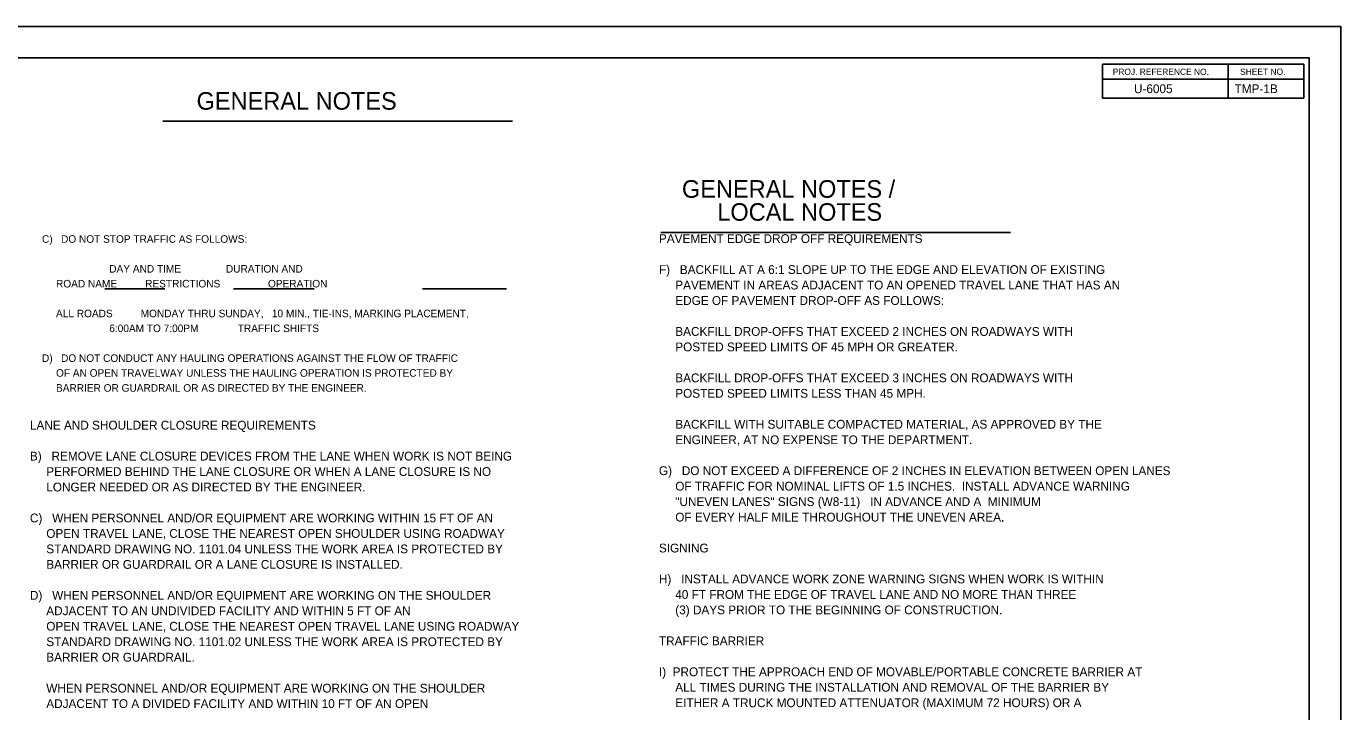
# Model space of a CAD drawing. Extents: x 762655 to 770567, y 650864 to 655190.
# Drawn here: x 769522 to 770567, y 654645 to 655190 of the extents above; entities that cross this region are included whole.
import ezdxf

# ---------------------------------------------------------------- set-up
doc = ezdxf.new("R2010")
doc.units = 0
for name, color, linetype in [('Default', 7, 'Continuous'), ('DEV BORDER CELL', 7, 'Continuous'), ('DEV TRANSPORTATION OPERATIONS PLAN SHEET', 7, 'Continuous'), ('Text', 7, 'Continuous')]:
    doc.layers.add(name, color=color, linetype=linetype)

msp = doc.modelspace()

# ---------------------------------------------------------------- linework, layer by layer
at = {"layer": 'Default'}
for p, q in [((769584.4, 654981.1), (769632.1, 654981.1)), ((769836.8, 654981.1), (769903.6, 654981.1))]:
    msp.add_line(p, q, dxfattribs=at)
at = {"layer": 'DEV BORDER CELL'}
for p, q in [((769630.5, 655114.3), (769908.5, 655114.3)), ((770026.5, 655026), (770304.4, 655026))]:
    msp.add_line(p, q, dxfattribs=at)
at = {"layer": 'DEV TRANSPORTATION OPERATIONS PLAN SHEET'}
msp.add_line((770477.6, 655147.7), (770537.6, 655147.7), dxfattribs=at)
for points in [[(770542, 655164.8), (769042, 655164.8), (769042, 654114.8), (770542, 654114.8)], [(770377.6, 655159.7), (770477.6, 655159.7), (770477.6, 655147.7), (770377.6, 655147.7)], [(770477.6, 655147.7), (770537.6, 655147.7), (770537.6, 655159.7), (770477.6, 655159.7)], [(770477.6, 655147.7), (770377.6, 655147.7), (770377.6, 655132.7), (770477.6, 655132.7)], [(770477.6, 655147.7), (770537.6, 655147.7), (770537.6, 655132.7), (770477.6, 655132.7)]]:
    msp.add_lwpolyline(points, close=True, dxfattribs=at)
at = {"layer": 'Text'}
msp.add_line((769686.7, 654981.1), (769750.9, 654981.1), dxfattribs=at)
msp.add_lwpolyline([(768879, 654089.8), (770567, 654089.8), (770567, 655189.8), (768879, 655189.8)], close=True, dxfattribs=at)

# ---------------------------------------------------------------- texts
at = {"layer": 'DEV TRANSPORTATION OPERATIONS PLAN SHEET'}
for s, height, p in [('PROJ. REFERENCE NO.', 4.999, (770385.7, 655151.2)), ('SHEET NO.', 5, (770487, 655151.2))]:
    msp.add_text(s, height=height, rotation=0.0006, dxfattribs=at).set_placement(p)
for s, height, p in [('U-6005', 7, (770402.6, 655136.7)), ('TMP-1B  ', 7, (770482.6, 655136.7)), ('GENERAL NOTES', 14, (769657.3, 655123.5)), ('GENERAL NOTES / ', 14, (770043.2, 655053.5)), ('LOCAL NOTES', 14, (770071.3, 655035.2))]:
    msp.add_text(s, height=height, dxfattribs=at).set_placement(p)
at = {"layer": 'Text'}
for s, height, p in [('       C)   DO NOT STOP TRAFFIC AS FOLLOWS:  ', 6, (769518.8, 655017.7)), ('       PAVEMENT EDGE DROP OFF REQUIREMENTS', 7, (770006.7, 655017.5)), ('                               DAY AND TIME                DURATION AND', 6, (769518.8, 654994)), ('       F)   BACKFILL AT A 6:1 SLOPE UP TO THE EDGE AND ELEVATION OF EXISTING', 7, (770006.7, 654992.9)), ('            ROAD NAME          RESTRICTIONS                 OPERATION', 6, (769518.8, 654982.2)), ('            PAVEMENT IN AREAS ADJACENT TO AN OPENED TRAVEL LANE THAT HAS AN ', 7, (770006.7, 654980.6)), ('            EDGE OF PAVEMENT DROP-OFF AS FOLLOWS:', 7, (770006.7, 654968.3)), ('            ALL ROADS          MONDAY THRU SUNDAY,   10 MIN., TIE-INS, MARKING PLACEMENT,', 6, (769518.8, 654958.5)), ('                               6:00AM TO 7:00PM              TRAFFIC SHIFTS', 6, (769518.8, 654946.7)), ('            BACKFILL DROP-OFFS THAT EXCEED 2 INCHES ON ROADWAYS WITH', 7, (770006.7, 654943.7)), ('       D)   DO NOT CONDUCT ANY HAULING OPERATIONS AGAINST THE FLOW OF TRAFFIC', 6, (769518.8, 654923)), ('            POSTED SPEED LIMITS OF 45 MPH OR GREATER.', 7, (770006.7, 654931.4)), ('            OF AN OPEN TRAVELWAY UNLESS THE HAULING OPERATION IS PROTECTED BY', 6, (769518.8, 654911.2)), ('            BACKFILL DROP-OFFS THAT EXCEED 3 INCHES ON ROADWAYS WITH', 7, (770006.7, 654906.8)), ('            BARRIER OR GUARDRAIL OR AS DIRECTED BY THE ENGINEER.', 6, (769518.8, 654899.3)), ('            POSTED SPEED LIMITS LESS THAN 45 MPH.', 7, (770006.7, 654894.5)), ('            BACKFILL WITH SUITABLE COMPACTED MATERIAL, AS APPROVED BY THE', 7, (770006.7, 654869.9)), ('       LANE AND SHOULDER CLOSURE REQUIREMENTS', 7, (769506.6, 654869.2)), ('            ENGINEER, AT NO EXPENSE TO THE DEPARTMENT.', 7, (770006.7, 654857.6)), ('       B)   REMOVE LANE CLOSURE DEVICES FROM THE LANE WHEN WORK IS NOT BEING', 7, (769506.6, 654844.6)), ('            PERFORMED BEHIND THE LANE CLOSURE OR WHEN A LANE CLOSURE IS NO ', 7, (769506.6, 654832.3)), ('       G)   DO NOT EXCEED A DIFFERENCE OF 2 INCHES IN ELEVATION BETWEEN OPEN LANES', 7, (770006.7, 654833)), ('            LONGER NEEDED OR AS DIRECTED BY THE ENGINEER.', 7, (769506.6, 654820)), ('            OF TRAFFIC FOR NOMINAL LIFTS OF 1.5 INCHES.  INSTALL ADVANCE WARNING', 7, (770006.7, 654820.7)), ('            "UNEVEN LANES" SIGNS (W8-11)   IN ADVANCE AND A  MINIMUM ', 7, (770006.7, 654808.4)), ('       C)   WHEN PERSONNEL AND/OR EQUIPMENT ARE WORKING WITHIN 15 FT OF AN', 7, (769506.6, 654795.4)), ('            OF EVERY HALF MILE THROUGHOUT THE UNEVEN AREA.', 7, (770006.7, 654796.1)), ('            OPEN TRAVEL LANE, CLOSE THE NEAREST OPEN SHOULDER USING ROADWAY ', 7, (769506.6, 654783.1)), ('            STANDARD DRAWING NO. 1101.04 UNLESS THE WORK AREA IS PROTECTED BY ', 7, (769506.6, 654770.8)), ('       SIGNING', 7, (770006.7, 654771.5)), ('            BARRIER OR GUARDRAIL OR A LANE CLOSURE IS INSTALLED.', 7, (769506.6, 654758.5)), ('       H)   INSTALL ADVANCE WORK ZONE WARNING SIGNS WHEN WORK IS WITHIN ', 7, (770006.7, 654746.9)), ('       D)   WHEN PERSONNEL AND/OR EQUIPMENT ARE WORKING ON THE SHOULDER', 7, (769506.6, 654733.9)), ('            40 FT FROM THE EDGE OF TRAVEL LANE AND NO MORE THAN THREE', 7, (770006.7, 654734.6)), ('            ADJACENT TO AN UNDIVIDED FACILITY AND WITHIN 5 FT OF AN', 7, (769506.6, 654721.6)), ('            (3) DAYS PRIOR TO THE BEGINNING OF CONSTRUCTION.', 7, (770006.7, 654722.3)), ('            OPEN TRAVEL LANE, CLOSE THE NEAREST OPEN TRAVEL LANE USING ROADWAY', 7, (769506.6, 654709.3)), ('            STANDARD DRAWING NO. 1101.02 UNLESS THE WORK AREA IS PROTECTED BY', 7, (769506.6, 654697)), ('       TRAFFIC BARRIER', 7, (770006.7, 654697.7)), ('            BARRIER OR GUARDRAIL.', 7, (769506.6, 654684.7)), ('       I)  PROTECT THE APPROACH END OF MOVABLE/PORTABLE CONCRETE BARRIER AT ', 7, (770006.7, 654673.1)), ('            ALL TIMES DURING THE INSTALLATION AND REMOVAL OF THE BARRIER BY', 7, (770006.7, 654660.8)), ('            WHEN PERSONNEL AND/OR EQUIPMENT ARE WORKING ON THE SHOULDER ', 7, (769506.6, 654660.1)), ('            ADJACENT TO A DIVIDED FACILITY AND WITHIN 10 FT OF AN OPEN', 7, (769506.6, 654647.8)), ('            EITHER A TRUCK MOUNTED ATTENUATOR (MAXIMUM 72 HOURS) OR A', 7, (770006.7, 654648.5))]:
    msp.add_text(s, height=height, dxfattribs=at).set_placement(p)

doc.saveas('drawing.dxf')
